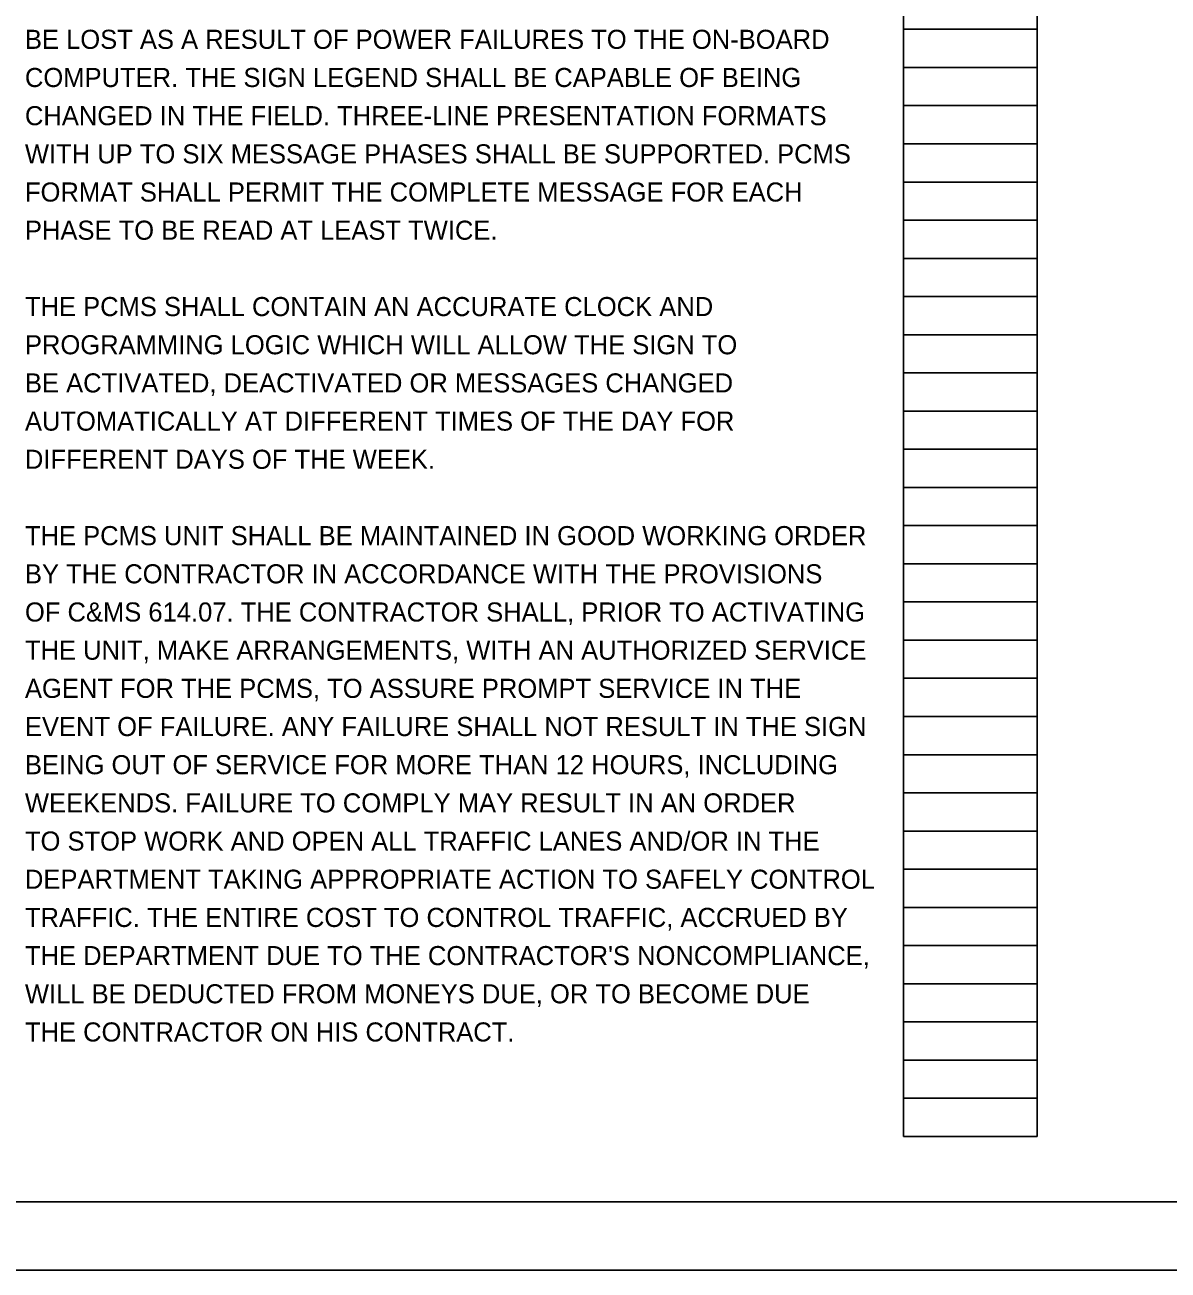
# Model space of a CAD drawing. Extents: x 0.1 to 34.1, y 0.1 to 22.1.
# Drawn here: x 17.32 to 25.7, y 0.1 to 9.23 of the extents above; entities that cross this region are included whole.
import ezdxf

# ---------------------------------------------------------------- set-up
doc = ezdxf.new("R2010")
doc.units = 0
for name, color, linetype in [('SH_Border', 7, 'Continuous'), ('SH_Cut_Line', 7, 'Continuous'), ('SH_Data', 7, 'Continuous'), ('SH_Text', 7, 'Continuous')]:
    doc.layers.add(name, color=color, linetype=linetype)

msp = doc.modelspace()

# ---------------------------------------------------------------- linework, layer by layer
at = {"layer": 'SH_Border'}
msp.add_lwpolyline([(1.576, 21.5994), (33.576, 21.5994), (33.576, 0.5994), (1.576, 0.5994)], close=True, dxfattribs=at)
at = {"layer": 'SH_Cut_Line'}
msp.add_lwpolyline([(0.076, 0.0994), (34.076, 0.0994), (34.076, 22.0994), (0.076, 22.0994)], close=True, dxfattribs=at)
at = {"layer": 'SH_Data'}
for p, q in [((23.756, 1.0794), (23.756, 21.2394)), ((24.736, 1.0794), (24.736, 21.2394)), ((23.756, 9.1994), (24.736, 9.1994)), ((23.756, 8.9194), (24.736, 8.9194)), ((23.756, 8.6394), (24.736, 8.6394)), ((23.756, 8.3594), (24.736, 8.3594)), ((23.756, 8.0794), (24.736, 8.0794)), ((23.756, 7.7994), (24.736, 7.7994)), ((23.756, 7.5194), (24.736, 7.5194)), ((23.756, 7.2394), (24.736, 7.2394)), ((23.756, 6.9594), (24.736, 6.9594)), ((23.756, 6.6794), (24.736, 6.6794)), ((23.756, 6.3994), (24.736, 6.3994)), ((23.756, 6.1194), (24.736, 6.1194)), ((23.756, 5.8394), (24.736, 5.8394)), ((23.756, 5.5594), (24.736, 5.5594)), ((23.756, 5.2794), (24.736, 5.2794)), ((23.756, 4.9994), (24.736, 4.9994)), ((23.756, 4.7194), (24.736, 4.7194)), ((23.756, 4.4394), (24.736, 4.4394)), ((23.756, 4.1594), (24.736, 4.1594)), ((23.756, 3.8794), (24.736, 3.8794)), ((23.756, 3.5994), (24.736, 3.5994)), ((23.756, 3.3194), (24.736, 3.3194)), ((23.756, 3.0394), (24.736, 3.0394)), ((23.756, 2.7594), (24.736, 2.7594)), ((23.756, 2.4794), (24.736, 2.4794)), ((23.756, 2.1994), (24.736, 2.1994)), ((23.756, 1.9194), (24.736, 1.9194)), ((23.756, 1.6394), (24.736, 1.6394)), ((23.756, 1.3594), (24.736, 1.3594)), ((23.756, 1.0794), (24.736, 1.0794))]:
    msp.add_line(p, q, dxfattribs=at)

# ---------------------------------------------------------------- texts
at = {"layer": 'SH_Text'}
for s, p in [('BE LOST AS A RESULT OF POWER FAILURES TO THE ON-BOARD', (17.3164, 9.0559)), ('COMPUTER. THE SIGN LEGEND SHALL BE CAPABLE OF BEING', (17.3164, 8.7759)), ('CHANGED IN THE FIELD. THREE-LINE PRESENTATION FORMATS', (17.3164, 8.4959)), ('WITH UP TO SIX MESSAGE PHASES SHALL BE SUPPORTED. PCMS', (17.3164, 8.2159)), ('FORMAT SHALL PERMIT THE COMPLETE MESSAGE FOR EACH', (17.3164, 7.9359)), ('PHASE TO BE READ AT LEAST TWICE.', (17.3164, 7.6559)), ('THE PCMS SHALL CONTAIN AN ACCURATE CLOCK AND', (17.3164, 7.0959)), ('PROGRAMMING LOGIC WHICH WILL ALLOW THE SIGN TO', (17.3164, 6.8159)), ('BE ACTIVATED, DEACTIVATED OR MESSAGES CHANGED', (17.3164, 6.5359)), ('AUTOMATICALLY AT DIFFERENT TIMES OF THE DAY FOR', (17.3164, 6.2559)), ('DIFFERENT DAYS OF THE WEEK.', (17.3164, 5.9759)), ('THE PCMS UNIT SHALL BE MAINTAINED IN GOOD WORKING ORDER', (17.3164, 5.4159)), ('BY THE CONTRACTOR IN ACCORDANCE WITH THE PROVISIONS', (17.3164, 5.1359)), ('OF C&MS 614.07. THE CONTRACTOR SHALL, PRIOR TO ACTIVATING', (17.3164, 4.8559)), ('THE UNIT, MAKE ARRANGEMENTS, WITH AN AUTHORIZED SERVICE', (17.3164, 4.5759)), ('AGENT FOR THE PCMS, TO ASSURE PROMPT SERVICE IN THE', (17.3164, 4.2959)), ('EVENT OF FAILURE. ANY FAILURE SHALL NOT RESULT IN THE SIGN', (17.3164, 4.0159)), ('BEING OUT OF SERVICE FOR MORE THAN 12 HOURS, INCLUDING', (17.3164, 3.7359)), ('WEEKENDS. FAILURE TO COMPLY MAY RESULT IN AN ORDER', (17.3164, 3.4559)), ('TO STOP WORK AND OPEN ALL TRAFFIC LANES AND/OR IN THE', (17.3164, 3.1759)), ('DEPARTMENT TAKING APPROPRIATE ACTION TO SAFELY CONTROL', (17.3164, 2.8959)), ('TRAFFIC. THE ENTIRE COST TO CONTROL TRAFFIC, ACCRUED BY', (17.3164, 2.6159)), ("THE DEPARTMENT DUE TO THE CONTRACTOR'S NONCOMPLIANCE,", (17.3164, 2.3359)), ('WILL BE DEDUCTED FROM MONEYS DUE, OR TO BECOME DUE', (17.3164, 2.0559)), ('THE CONTRACTOR ON HIS CONTRACT.', (17.3164, 1.7759))]:
    msp.add_text(s, height=0.14, dxfattribs=at).set_placement(p)

doc.saveas('drawing.dxf')
